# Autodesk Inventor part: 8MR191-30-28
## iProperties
Created: 2007-04
Part Number: 8MR191-30-28
Document SubType Name: Modeling
Designer: Darius
Author: Darius
Translation Standard: STEP AP203
File Name: 8MR191-30-28.STEP
Preprocessor: SolidWorks 2003240
Postprocessor: Build: 270, Release: 10 SP2 - Date: Mon 09/26/2005
Sent Units: MILLIMETERS
Uncertainty: 1e-05
